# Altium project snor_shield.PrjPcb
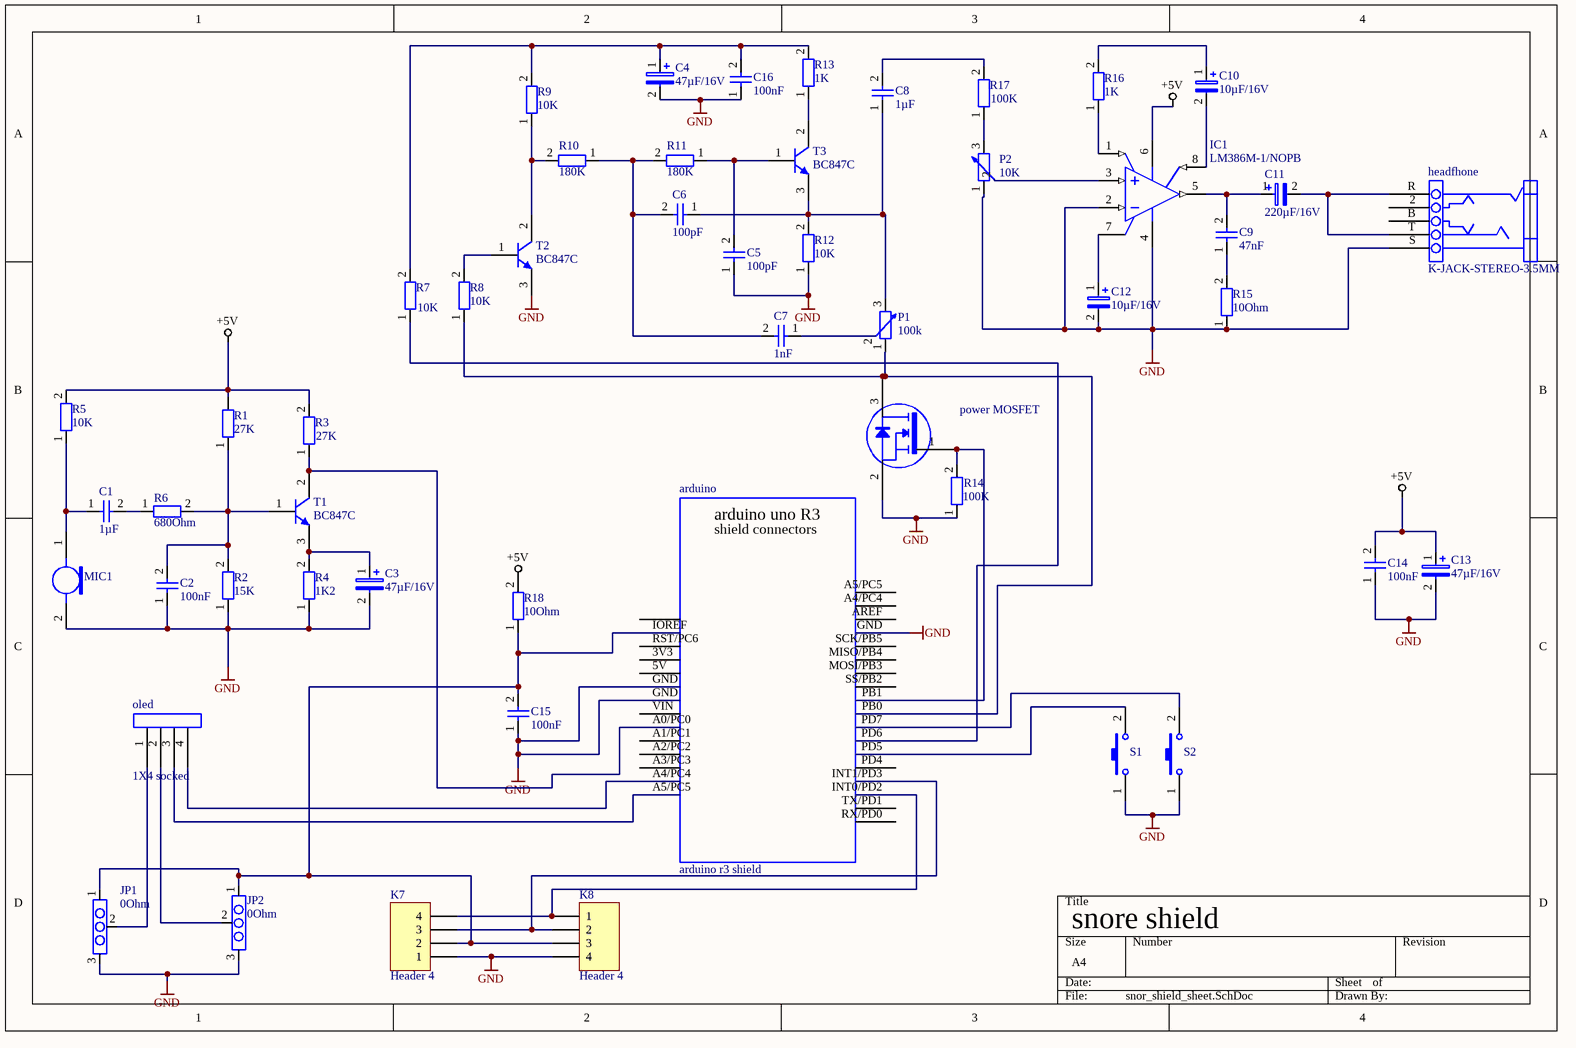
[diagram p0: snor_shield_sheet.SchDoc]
1 sheet, 51 parts. Net scope: global (net labels, ports and power ports of the same name join across sheets).
Board files: PCB_snoreshield.PcbDoc, pcb_snore_shield.PcbDoc

## Sheet snor_shield_sheet.SchDoc: snore shield
size A4

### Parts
arduino  arduino r3 shield  [arduino]
C1  value 1µF  [SMD 0805]  (hidden comment: Capitor)
C2  value 100nF  [SMD 0805]  (hidden comment: Capitor)
C3  value 47µF/16V  [elektor trans 2]  (hidden comment: Cap Pol1)
C4  value 47µF/16V  [elektor trans 2]  (hidden comment: Cap Pol1)
C5  value 100pF  [SMD 0805]  (hidden comment: Capitor)
C6  value 100pF  [SMD 0805]  (hidden comment: Capitor)
C7  value 1nF  [SMD 0805]  (hidden comment: Capitor)
C8  value 1µF  [SMD 0805]  (hidden comment: Capitor)
C9  value 47nF  [SMD 0805]  (hidden comment: Capitor)
C10  value 10µF/16V  [elecktor trans 1]  (hidden comment: Cap Pol1)
C11  value 220µF/16V  [elektor trans 3]  (hidden comment: Cap Pol1)
C12  value 10µF/16V  [elecktor trans 1]  (hidden comment: Cap Pol1)
C13  value 47µF/16V  [elektor trans 2]  (hidden comment: Cap Pol1)
C14  value 100nF  [SMD 0805]  (hidden comment: Cap)
C15  value 100nF  [SMD 0805]  (hidden comment: Capitor)
C16  value 100nF  [SMD 0805]  (hidden comment: Capitor)
headfhone  K-JACK-STEREO-3.5MM  [adioplug3.5mm]
IC1  LM386M-1/NOPB  [LM386M-1/NOPB]
JP1  value 0Ohm  [soldeer_jumper]  (hidden comment: Res2)
JP2  value 0Ohm  [soldeer_jumper]  (hidden comment: Res2)
K7  Header 4  [HDR1X4]
K8  Header 4  [HDR1X4]
MIC1  Mic2  [Electret Condenser Microphone]  (value not drawn)
mosfet  power MOSFET  [power mosfet]
oled  1X4 socked  [oled scherm]
P1  value 100k  [potmeter]  (hidden comment: Res Adj2)
P2  value 10K  [potmeter]  (hidden comment: Res Adj2)
R1  value 27K  [SMD 0805]  (hidden comment: weerstand)
R2  value 15K  [SMD 0805]  (hidden comment: weerstand)
R3  value 27K  [SMD 0805]  (hidden comment: weerstand)
R4  value 1K2  [SMD 0805]  (hidden comment: weerstand)
R5  value 10K  [SMD 0805]  (hidden comment: weerstand)
R6  value 680Ohm  [SMD 0805]  (hidden comment: weerstand)
R7  value 10K  [SMD 0805]  (hidden comment: weerstand)
R8  value 10K  [SMD 0805]  (hidden comment: weerstand)
R9  value 10K  [SMD 0805]  (hidden comment: weerstand)
R10  value 180K  [SMD 0805]  (hidden comment: weerstand)
R11  value 180K  [SMD 0805]  (hidden comment: weerstand)
R12  value 10K  [SMD 0805]  (hidden comment: weerstand)
R13  value 1K  [SMD 0805]  (hidden comment: weerstand)
R14  value 100K  [SMD 0805]  (hidden comment: weerstand)
R15  value 10Ohm  [SMD 0805]  (hidden comment: weerstand)
R16  value 1K  [SMD 0805]  (hidden comment: weerstand)
R17  value 100K  [SMD 0805]  (hidden comment: Res2)
R18  value 10Ohm  [SMD 0805]  (hidden comment: weerstand)
S1  SW-PB  [switch]  (value not drawn)
S2  SW-PB  [switch]  (value not drawn)
T1  BC847C  [bipolar BjT]
T2  BC847C  [bipolar BjT]
T3  BC847C  [bipolar BjT]

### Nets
+5V: C13.1 C14.2 IC1.6(VS) R1.2 R3.2 R5.2 R18.2
GND: arduino.GND C2.1 C3.2 C4.2 C5.1 C12.2 C13.2 C14.1 C15.1 C16.1 headfhone.S IC1.2(IN-) IC1.4(GND) JP1.3 JP2.3 K7.1 K8.4 MIC1.2(uitgang) mosfet.2 P2.1 R2.1 R4.1 R12.1 R14.1 R15.1 S1.1 S2.1 T2.3(E)
Netarduino_A0/PC0: arduino.A0/PC0 R3.1 T1.2(C)
Netarduino_A4/PC4: arduino.A4/PC4 oled.4
Netarduino_A5/PC5: arduino.A5/PC5 oled.3
Netarduino_INT0/PD2: arduino.INT0/PD2 K7.4 K8.1
Netarduino_INT1/PD3: arduino.INT1/PD3 K7.3 K8.2
Netarduino_IOREF: arduino.IOREF C15.2 JP1.1 JP2.1 K7.2 K8.3 R18.1
Netarduino_PB0: arduino.PB0 mosfet.3 P1.1 R8.1
Netarduino_PB1: arduino.PB1 mosfet.1 R14.2
Netarduino_PD5: arduino.PD5 S1.2
Netarduino_PD6: arduino.PD6 R7.1
Netarduino_PD7: arduino.PD7 S2.2
NetC1_1: C1.1 MIC1.1 R5.1
NetC1_2: C1.2 R6.1
NetC2_2: C2.2 R1.1 R2.2 R6.2 T1.1(B)
NetC3_1: C3.1 R4.2 T1.3(E)
NetC4_1: C4.1 C16.2 R7.2 R9.2 R13.2
NetC5_2: C5.2 R11.1 T3.1(B)
NetC6_1: C6.1 C8.1 P1.3 R12.2 T3.3(E)
NetC6_2: C6.2 C7.2 R10.1 R11.2
NetC7_1: C7.1 P1.2
NetC8_2: C8.2 R17.2
NetC9_1: C9.1 R15.2
NetC9_2: C9.2 C11.1 IC1.5(VOUT)
NetC10_1: C10.1 R16.2
NetC10_2: C10.2 IC1.8(GAIN)
NetC11_2: C11.2 headfhone.R headfhone.T
NetC12_1: C12.1 IC1.7(BYPASS)
NetIC1_1: IC1.1(GAIN) R16.1
NetIC1_3: IC1.3(IN+) P2.2
NetJP1_2: JP1.2 oled.1
NetJP2_2: JP2.2 oled.2
NetP2_3: P2.3 R17.1
NetR8_2: R8.2 T2.1(B)
NetR9_1: R9.1 R10.2 T2.2(C)
NetR13_1: R13.1 T3.2(C)

Not connected (* = marked no-connect by the designer): arduino 3V3(26) 5V(27) ?1(23) A1/PC1(32) A2/PC2(33) A3/PC3(34) AREF(39) MISO/PB4(42) MOSI/PB3(43) PD4(50) RST/PC6(25) RX/PD0(54) SCK/PB5(41) SS/PB2(44) TX/PD1(53) VIN(30); headfhone 2 B(3)

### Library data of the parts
C1 C2 C5-C9 C14-C16 = Capitor: Capacitor
C3 C4 C13 = Cap Pol1_1: Polarized Capacitor (Radial) 47µF
C10 C12 = Cap Pol1: Polarized Capacitor (Radial) 10µF
C11 = Cap Pol1_2: Polarized Capacitor (Radial) 220µF
JP1 JP2 = solderjump: Resistor
K7 = Header 4: Header, 4-Pin,2mm
K8 = Header 4: Header, 4-Pin
MIC1 = Mic2: Microphone
P1 = Res Adj2: Variable Resistor 10K; Set Position: 0.5
P2 = Res Adj2_1: Variable Resistor; Set Position: 0.5
R1-R18 = weerstand: Resistor
S1 S2 = switch
T1-T3 = BJT: NPN General Purpose Amplifier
